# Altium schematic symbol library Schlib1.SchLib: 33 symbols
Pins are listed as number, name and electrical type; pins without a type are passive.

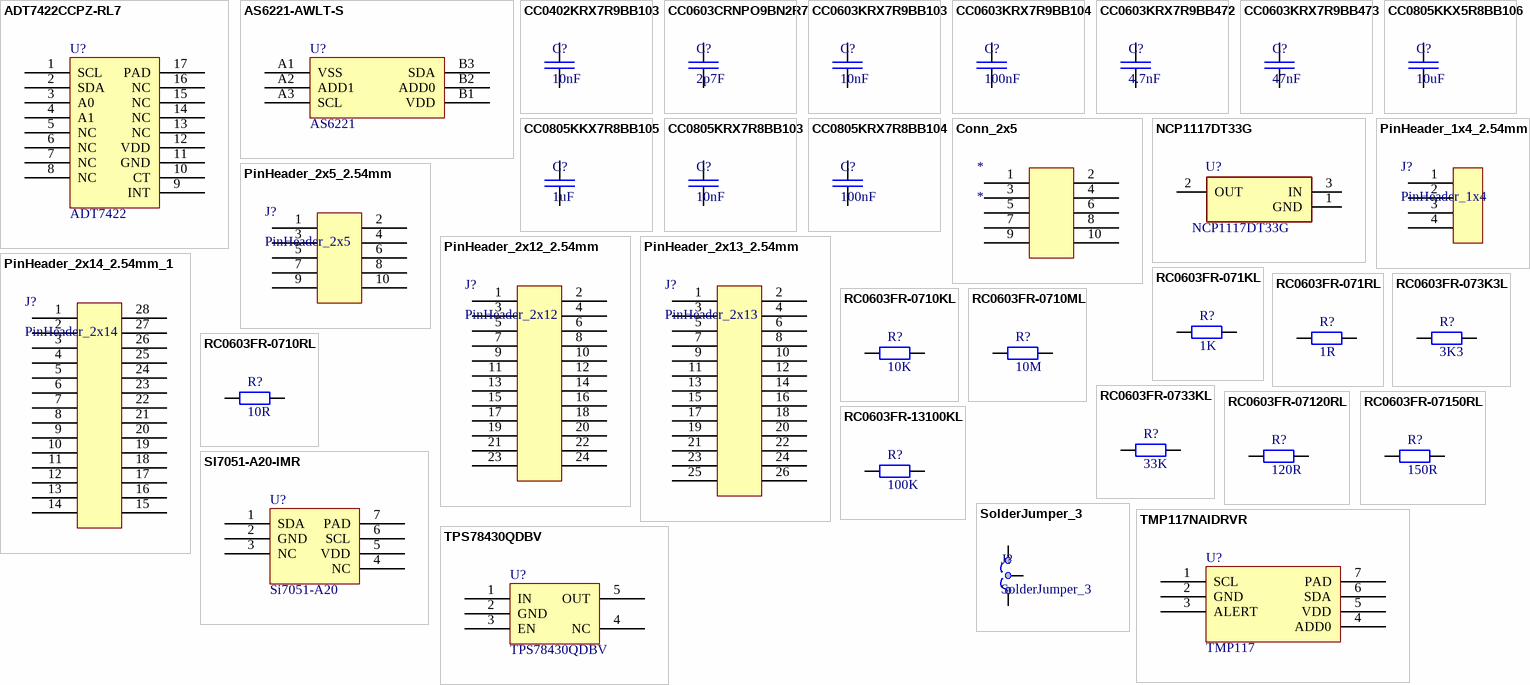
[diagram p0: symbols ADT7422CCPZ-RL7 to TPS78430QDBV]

## ADT7422CCPZ-RL7
designator U?, comment ADT7422
ADT7422 Temperature Sensor, ±0.1°C Accuracy, 16b, Digital I2C / -40°C bis 125°C 16-LFCSP-WQ (4x4)
footprint ADT7422_QFN
pins: 1 SCL, 2 SDA, 3 A0, 4 A1, 5 NC, 6 NC, 7 NC, 8 NC, 9 INT, 10 CT, 11 GND, 12 VDD, 13 NC, 14 NC, 15 NC, 16 NC, 17 PAD

## AS6221-AWLT-S
designator U?, comment AS6221
AS6221 Temperature Sensor Digital -40°C ~ 125°C 16b 6-WLCSP (1.5x1.03)
footprint AS6221_BGA
pins: A1 VSS, A2 ADD1, A3 SCL, B1 VDD, B2 ADD0, B3 SDA

## CC0402KRX7R9BB103
designator C?, comment 10nF
CAP 10nF SM0402 X7R 50V YAGEO CC2; Manufacturer Part Number: CC0603KRX7R9BB103; Tolerance (%): 10; Voltage Rating (Volts): 50
footprint CAP_SM0402_YAGEOCC2_N (Capacitor, Yageo CC Class2, SM0402, IPC Medium Density)
pins: 1, 2

## CC0603CRNPO9BN2R7
designator C?, comment 2p7F
CAP 2.7pF (2p7F) SM0603 NPO 50V YAGEO CC2; Manufacturer Part Number: CC0603CRNPO9BN2R7; Tolerance (%): 10; Voltage Rating (Volts): 50
footprint CAP_SM0603_YAGEOCC2_N (Capacitor, Yageo CC Class2, SM0603, IPC Medium Density)
pins: 1, 2

## CC0603KRX7R9BB103
designator C?, comment 10nF
CAP 10nF SM0603 X7R 50V YAGEO CC2; Manufacturer Part Number: CC0603KRX7R9BB103; Tolerance (%): 10; Voltage Rating (Volts): 50
footprint CAP_SM0603_YAGEOCC2_N (Capacitor, Yageo CC Class2, SM0603, IPC Medium Density)
pins: 1, 2

## CC0603KRX7R9BB104
designator C?, comment 100nF
CAP 100nF SM0603 X7R 50V YAGEO CC2; Manufacturer Part Number: CC0603KRX7R9BB104; Tolerance (%): 10; Voltage Rating (Volts): 50
footprint CAP_SM0603_YAGEOCC2_N (Capacitor, Yageo CC Class2, SM0603, IPC Medium Density)
pins: 1, 2

## CC0603KRX7R9BB472
designator C?, comment 4.7nF
CAP 4.7nF SM0603 X7R 50V YAGEO CC2; Manufacturer Part Number: CC0603KRX7R9BB223; Tolerance (%): 10; Voltage Rating (Volts): 50
footprint CAP_SM0603_YAGEOCC2_N (Capacitor, Yageo CC Class2, SM0603, IPC Medium Density)
pins: 1, 2

## CC0603KRX7R9BB473
designator C?, comment 47nF
CAP 47nF SM0603 X7R 50V YAGEO CC2; Manufacturer Part Number: CC0603KRX7R9BB223; Tolerance (%): 10; Voltage Rating (Volts): 50
footprint CAP_SM0603_YAGEOCC2_N (Capacitor, Yageo CC Class2, SM0603, IPC Medium Density)
pins: 1, 2

## CC0805KKX5R8BB106
designator C?, comment 10uF
CAP 10uF SM0805 X5R 16V YAGEO CC2; Manufacturer Part Number: CC0805KKX7R8BB225; Tolerance (%): 10; Voltage Rating (Volts): 25
footprint CAP_SM0805_YAGEOCC2_N (Capacitor, Yageo CC Class2, SM0805, IPC Medium Density)
pins: 1, 2

## CC0805KKX7R8BB105
designator C?, comment 1uF
CAP 1uF SM0805 X7R 25V YAGEO CC2; Manufacturer Part Number: CC0805KKX7R8BB105; Tolerance (%): 10; Voltage Rating (Volts): 25
footprint CAP_SM0805_YAGEOCC2_N (Capacitor, Yageo CC Class2, SM0805, IPC Medium Density)
pins: 1, 2

## CC0805KRX7R8BB103
designator C?, comment 10nF
CAP 10nF SM0805 X7R 25V YAGEO CC2; Manufacturer Part Number: CC0805KRX7R8BB103; Tolerance (%): 10; Voltage Rating (Volts): 25
footprint CAP_SM0805_YAGEOCC2_N (Capacitor, Yageo CC Class2, SM0805, IPC Medium Density)
pins: 1, 2

## CC0805KRX7R8BB104
designator C?, comment 100nF
CAP 100nF SM0805 X7R 25V YAGEO CC2; Manufacturer Part Number: CC0805KRX7R8BB104; Tolerance (%): 10; Voltage Rating (Volts): 25
footprint CAP_SM0805_YAGEOCC2_N (Capacitor, Yageo CC Class2, SM0805, IPC Medium Density)
pins: 1, 2

## Conn_2x5
designator *
pins: 1, 2, 3, 4, 5, 6, 7, 8, 9, 10

## NCP1117DT33G
designator U?
Linear Voltage Regulator IC Positive Fixed 1 Output 1A DPAK; Manufacturer_Name: onsemi; Geometry.Height: 2.51mm
footprint NCP1117DT33G
pins: 1 GND, 2 OUT, 3 IN

## PinHeader_1x4_2.54mm
designator J?, comment PinHeader_1x4
PinHeader_1x4 2.54mm Pitch
footprint PinHeader_1x4_2.54mm (Footprint not found)
pins: 1, 2, 3, 4

## PinHeader_2x5_2.54mm
designator J?, comment PinHeader_2x5
PinHeader_2x5 2.54mm Pitch
footprint PinHeader_2x5_2.54mm (Footprint not found)
pins: 1, 2, 3, 4, 5, 6, 7, 8, 9, 10

## PinHeader_2x12_2.54mm
designator J?, comment PinHeader_2x12
PinHeader_2x12 2.54mm Pitch
footprint PinHeader_2x12_2.54mm
pins: 1, 2, 3, 4, 5, 6, 7, 8, 9, 10, 11, 12, 13, 14, 15, 16, 17, 18, 19, 20, 21, 22, 23, 24

## PinHeader_2x13_2.54mm
designator J?, comment PinHeader_2x13
PinHeader_2x13 2.54mm Pitch
footprint PinHeader_2x13_2.54mm (Footprint not found)
pins: 1, 2, 3, 4, 5, 6, 7, 8, 9, 10, 11, 12, 13, 14, 15, 16, 17, 18, 19, 20, 21, 22, 23, 24, 25, 26

## PinHeader_2x14_2.54mm_1
designator J?, comment PinHeader_2x14
PinHeader_2x14 2.54mm Pitch
footprint PinHeader_2x14_2.54mm (Footprint not found)
pins: 1, 2, 3, 4, 5, 6, 7, 8, 9, 10, 11, 12, 13, 14, 15, 16, 17, 18, 19, 20, 21, 22, 23, 24, 25, 26, 27, 28

## RC0603FR-071KL
designator R?, comment 1K
RES 1K SM0603 YAGEO RC_L; Manufacturer Part Number: RC0603FR-071KL; Power (Watts): 0.1; Resistance (Ohms): 1000; Tolerance (%): 1
footprint RES_SM0603_YAGEORC_N (Resistor, Yageo RC_L, SM0603, IPC Medium Density)
pins: 1, 2

## RC0603FR-071RL
designator R?, comment 1R
RES 1R SM0603YAGEO RC_L; Manufacturer: Yageo; Manufacturer Part Number: RC0805FR-0710RL; Power (Watts): 0.125; Resistance (Ohms): 10; Tolerance (%): 1
footprint RES_SM0603_YAGEORC_N (Resistor, Yageo RC_L, SM0603, IPC Medium Density)
pins: 1, 2

## RC0603FR-073K3L
designator R?, comment 3K3
RES 3.3K SM0603 YAGEO RC_L; Manufacturer Part Number: RC0603FR-0710KL; Power (Watts): 0.1; Resistance (Ohms): 10000; Tolerance (%): 1
footprint RES_SM0603_YAGEORC_N (Resistor, Yageo RC_L, SM0603, IPC Medium Density)
pins: 1, 2

## RC0603FR-0710KL
designator R?, comment 10K
RES 10K SM0603 YAGEO RC_L; Manufacturer Part Number: RC0603FR-0710KL; Power (Watts): 0.1; Resistance (Ohms): 10000; Tolerance (%): 1
footprint RES_SM0603_YAGEORC_N (Resistor, Yageo RC_L, SM0603, IPC Medium Density)
pins: 1, 2

## RC0603FR-0710ML
designator R?, comment 10M
RES 10M SM0603 YAGEO RC_L; Manufacturer Part Number: RC0603FR-0710ML; Power (Watts): 0.1; Resistance (Ohms): 10000000; Tolerance (%): 1
footprint RES_SM0603_YAGEORC_N (Resistor, Yageo RC_L, SM0603, IPC Medium Density)
pins: 1, 2

## RC0603FR-0710RL
designator R?, comment 10R
RES 10R SM0603 YAGEO RC_L; Manufacturer Part Number: RC0603FR-0710RL; Power (Watts): 0.1; Resistance (Ohms): 10; Tolerance (%): 1
footprint RES_SM0603_YAGEORC_N (Resistor, Yageo RC_L, SM0603, IPC Medium Density)
pins: 1, 2

## RC0603FR-0733KL
designator R?, comment 33K
RES 33K SM0603 YAGEO RC_L; Manufacturer Part Number: RC0603FR-0733KL; Power (Watts): 0.1; Resistance (Ohms): 33000; Tolerance (%): 1
footprint RES_SM0603_YAGEORC_N (Resistor, Yageo RC_L, SM0603, IPC Medium Density)
pins: 1, 2

## RC0603FR-07120RL
designator R?, comment 120R
RES 120R SM0603 YAGEO RC_L; Manufacturer Part Number: RC0603FR-07120RL; Power (Watts): 0.1; Resistance (Ohms): 120; Tolerance (%): 1
footprint RES_SM0603_YAGEORC_N (Resistor, Yageo RC_L, SM0603, IPC Medium Density)
pins: 1, 2

## RC0603FR-07150RL
designator R?, comment 150R
RES 150R SM0603 YAGEO RC_L; Manufacturer Part Number: RC0603FR-07150RL; Power (Watts): 0.1; Resistance (Ohms): 150; Tolerance (%): 1
footprint RES_SM0603_YAGEORC_N (Resistor, Yageo RC_L, SM0603, IPC Medium Density)
pins: 1, 2

## RC0603FR-13100KL
designator R?, comment 100K
RES 100K SM0603 YAGEO RC_L; Manufacturer Part Number: RC0603FR-13100KL; Power (Watts): 0.1; Resistance (Ohms): 100000; Tolerance (%): 1
footprint RES_SM0603_YAGEORC_N (Resistor, Yageo RC_L, SM0603, IPC Medium Density)
pins: 1, 2

## SI7051-A20-IMR
designator U?, comment Si7051-A20
Si7051-A20 Temperature Sensor ±0.1°C maximum accuracy, Digital I2C, -40°C ~ 125°C 14b 6-DFN (3x3)
footprint SI7050/1/2/3/4/5 (SON, 6-Leads, Body 3,00x3,00mm, Pitch 1,00mm, Thermal Pad 2,50x1,50mm, IPC Medium Density)
pins: 1 SDA, 2 GND, 3 NC, 4 NC, 5 VDD, 6 SCL, 7 PAD

## SolderJumper_3
designator J?
footprint SolderJumper3_1
pins: 1, 2, 3

## TMP117NAIDRVR
designator U?, comment TMP117
TMP117 High-Accuracy, Low-Power, Digital Temperature Sensor, -55°C bis 150°C, 16b 6-WSON (2x2)
footprint TMP117(N/M)AIDRV_WSON (SON127P600-8N)
pins: 1 SCL, 2 GND, 3 ALERT, 4 ADD0, 5 VDD, 6 SDA, 7 PAD

## TPS78430QDBV
designator U?
TPS78430QDBV LDO 3.0V 300mA
footprint TPS784XXXQDBVRQ1_SOT23 (SOT23, 5-Leads, Body 2,90x2,80mm, Pitch 0,95mm, IPC Medium Density)
pins: 1 IN, 2 GND, 3 EN, 4 NC, 5 OUT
